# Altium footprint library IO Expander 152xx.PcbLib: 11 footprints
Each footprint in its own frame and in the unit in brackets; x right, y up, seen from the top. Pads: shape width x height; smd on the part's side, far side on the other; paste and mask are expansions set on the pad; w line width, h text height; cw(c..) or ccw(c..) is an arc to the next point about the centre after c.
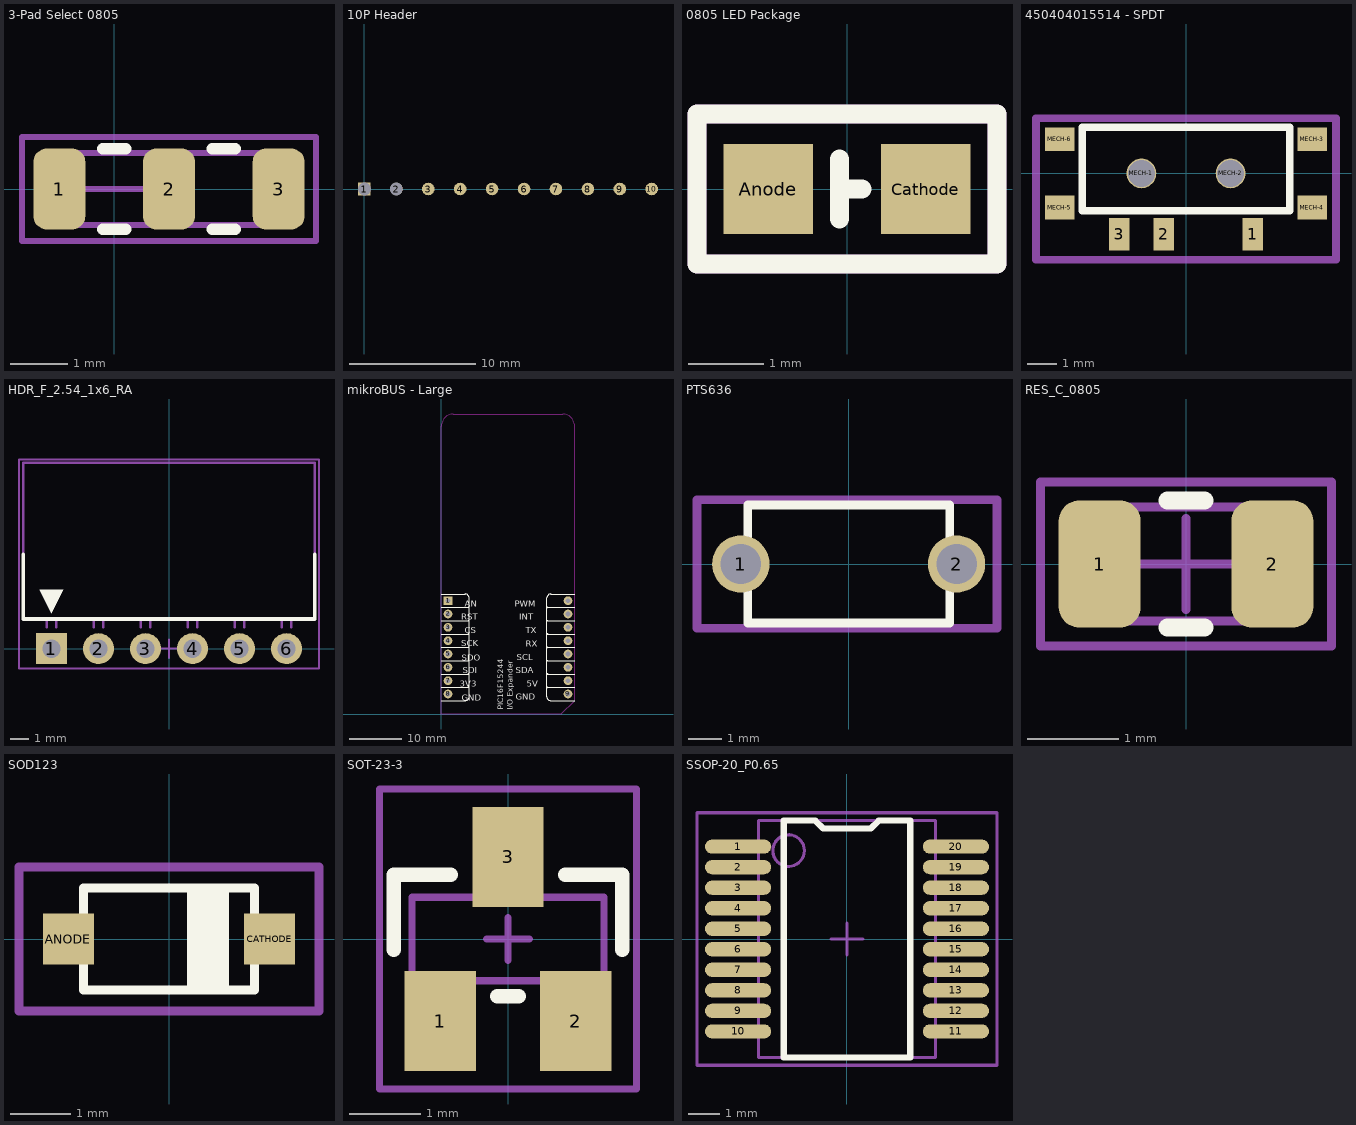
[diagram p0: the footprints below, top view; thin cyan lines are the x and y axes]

## 3-Pad Select 0805 [mm] "Chip Resistor, 2-Leads, Body 2.0x1.3mm, IPC Medium Density"
height 0.6
pads (3):
  rrect50% 0.9x1.4 smd: 1(-0.95,0) 2(0.95,0) 3(2.85,0)
Top Overlay:
  lines w0.2: -0.2,-0.7 0.2,-0.7 ; -0.2,0.7 0.2,0.7 ; 1.7,-0.7 2.1,-0.7 ; 1.7,0.7 2.1,0.7
Top Assembly:
  lines w0.1: -1,-0.625 -1,0.625 2.6,0.625 2.6,-0.625 -1,-0.625
  text ".Designator" at -0.8,-0.2 h0.45
Top 3D Body:
  lines w0.1: 0.6,-0.625 2.6,-0.625 ; 0.6,0.625 2.6,0.625 ; 2.6,-0.625 2.6,0.625 ; 2.6,-0.625 -1,-0.625 -1,0.625 2.6,0.625
Top Courtyard:
  lines w0.1: -0.5,0 0.5,0 ; -1.6,-0.9 3.5,-0.9 3.5,0.9 -1.6,0.9 -1.6,-0.9
3D body "RES_0805.step": height 0.78, standoff 0, extent -1,-0.625 1,0.625
3D body "RES_0805.step": height 0.78, standoff 0, extent 0.6,-0.625 2.6,0.625

## 10P Header [mm] "Footprint for 10P 2.54mm Header"
pads (10):
  rect 1x1 hole 1.02: 1(0,0)
  round 1 hole 1.02: 2(2.54,0)
  round 1 all layers, no hole: 3(5.08,0) 4(7.62,0) 5(10.16,0) 6(12.7,0) 7(15.24,0) 8(17.78,0) 9(20.32,0) 10(22.86,0)

## 0805 LED Package [mm] "0805 Package for LED"
height 2.6
pads (2):
  rect 1.2x1.2 smd: Anode(-1.05,0) Cathode(1.05,0)
Top Overlay:
  lines w0.254: -0.1,-0.4 -0.1,0.4 ; -0.1,0 0.2,0 ; -2,-1 -2,1 2,1 2,-1 -2,-1
Top Courtyard:
  lines w0.254: -2,-1 -2,1 2,1 2,-1 -2,-1
  text ".designator" at -1.8,-0.367 h1

## 450404015514 - SPDT [mm] "SPDT Switch"
pads (9):
  rect 0.7x1.1 smd: 1(2.25,-2.05) 2(-0.75,-2.05) 3(-2.25,-2.05)
  round 1 hole 0.9 unplated: MECH-1(-1.5,0) MECH-2(1.5,0)
  rect 1x0.8 smd: MECH-3(4.25,1.15) MECH-4(4.25,-1.15) MECH-5(-4.25,-1.15) MECH-6(-4.25,1.15)
Top Overlay:
  lines w0.254: -3.5,-1.25 3.5,-1.25 3.5,1.55 -3.5,1.55 -3.5,-1.25
Top Courtyard:
  lines w0.254: -5.05,-2.9 5.05,-2.9 5.05,1.85 -5.05,1.85 -5.05,-2.9

## HDR_F_2.54_1x6_RA [mil] "Header Female Right Angle 6 Way 2.54mm Pitch"
height 102.36
pads (6):
  rect 66x66 hole 39: 1(-250,0)
  round 66 hole 39: 2(-150,0) 3(-50,0) 4(50,0) 5(150,0) 6(250,0)
Top Overlay:
  region: -250,75 -275,125 -225,125
  lines w7.87: -310,200 -310,62.99 310,62.99 310,200
Top Assembly:
  lines w5: -260,45 -260,65 ; -240,45 -240,65 ; -160,45 -160,65 ; -140,45 -140,65 ; -60,45 -60,65 ; -40,45 -40,65 ; 40,45 40,65 ; 60,45 60,65 ; 140,45 140,65 ; 160,45 160,65 ; 240,45 240,65 ; 260,45 260,65 ; -310,65 -310,395 310,395 310,65 -310,65
  text ".Designator" at -5,75 h30
Top Courtyard:
  lines w3.94: -19.68,0 19.68,0 ; 0,-19.68 0,19.68 ; -319,-42 319,-42 319,402 -319,402 -319,-42
3D body "HDR_F_254_1x6 RA.step": height 96.71, standoff -98.29, extent -309.99,-7.99 310.01,395

## mikroBUS - Large [mil]
height 47.24
pads (16):
  rect 65x65 hole 35: 1(50,850)
  round 65 hole 35: 2(50,750) 3(50,650) 4(50,550) 5(50,450) 6(50,350) 7(50,250) 8(50,150) 9(950,150) 10(950,250) 11(950,350) 12(950,450) 13(950,550) 14(950,650) 15(950,750) 16(950,850)
Top Overlay:
  lines w6: 0,100 180.05,100 ; 0,900 180,900 cw(c180,872.05) 207.95,872.05 ; 180.05,100.05 ccw(c180.05,128) 208,128 208,872.05 ; 208,805 cw(c203,805) 203,800 ; 792,805 ccw(c797,805) 797,800 ; 792,872.05 792,128 ccw(c819.95,128) 819.95,100.05 ; 792.05,872.05 cw(c820,872.05) 820,900 1000,900 ; 819.95,100 1000,100 ; 203,200 cw(c203,195) 208,195 ccw(c203,195) 203,200 ; 203,200 ccw(c203,205) 208,205 208,295 ; 203,200 0,200 203,200 ; 203,300 cw(c203,295) 208,295 ; 203,300 ccw(c203,305) 208,305 208,395 ; 203,300 cw(c203,295) 208,295 ; 203,300 0,300 203,300 ; 203,400 cw(c203,395) 208,395 ; 203,400 ccw(c203,405) 208,405 208,495 ; 203,400 cw(c203,395) 208,395 ; 203,400 0,400 203,400 ; 203,500 cw(c203,495) 208,495 ; 203,500 ccw(c203,505) 208,505 208,595 ; 203,500 cw(c203,495) 208,495 ; 203,500 0,500 203,500 ; 203,600 cw(c203,595) 208,595 ; 203,600 ccw(c203,605) 208,605 208,695 ; 203,600 cw(c203,595) 208,595 ; 203,600 0,600 203,600 ; 203,700 cw(c203,695) 208,695 ; 203,700 ccw(c203,705) 208,705 208,795 ; 203,700 cw(c203,695) 208,695 ; 203,700 0,700 203,700 ; 203,800 cw(c203,795) 208,795 ; 203,800 cw(c203,795) 208,795 ; 203,800 0,800 203,800 ; 792,295 cw(c797,295) 797,300 ; 792,295 cw(c797,295) 797,300 ; 792,295 792,205 ccw(c797,205) 797,200 ; 792,395 cw(c797,395) 797,400 ; 792,395 cw(c797,395) 797,400 ; 792,395 792,305 ccw(c797,305) 797,300 ; 792,495 cw(c797,495) 797,500 ; 792,495 cw(c797,495) 797,500 ; 792,495 792,405 ccw(c797,405) 797,400 ; 792,595 cw(c797,595) 797,600 ; 792,595 cw(c797,595) 797,600 ; 792,595 792,505 ccw(c797,505) 797,500 ; 792,695 cw(c797,695) 797,700 ; 792,695 cw(c797,695) 797,700 ; 792,695 792,605 ccw(c797,605) 797,600 ; 792,795 cw(c797,795) 797,800 ; 792,795 cw(c797,795) 797,800 ; 792,795 792,705 ccw(c797,705) 797,700 ; 797,200 ccw(c797,195) 792,195 cw(c797,195) 797,200 ; 797,200 1000,200 797,200 ; 797,300 1000,300 797,300 ; 797,400 1000,400 797,400 ; 797,500 1000,500 797,500 ; 797,600 1000,600 797,600 ; 797,700 1000,700 797,700 ; 797,800 1000,800 797,800
  text "PIC16F15244 / I/O Expander" at 550,30 h70.87
  text "CS" at 175,590 h78.74
  text "PWM" at 550,790 h78.74
  text "INT" at 585,690 h78.74
  text "TX" at 634.78,590 h78.74
  text "RX" at 634.78,488.89 h78.74
  text "SCL" at 565,389.55 h78.74
  text "SDA" at 560,290 h78.74
  text "5V" at 640,190 h78.74
  text "GND" at 560,90 h78.74
  text "AN" at 175,790 h78.74
  text "GND" at 155,85 h78.74
  text "3V3" at 140,190 h78.74
  text "SDI" at 160.31,290 h78.74
  text "SDO" at 155,385 h78.74
  text "SCK" at 150,495 h78.74
  text "RST" at 150,690 h78.74
Bottom Overlay:
  lines w6: 0,100 221.05,100 ; 0,900 221,900 cw(c221,872.05) 248.95,872.05 248.95,128.05 ; 221.05,100.05 ccw(c221.05,128) 249,128 ; 249,128.05 249,195 ccw(c244,195) 244,200 ; 249,805 cw(c244,805) 244,800 ; 751,128 ccw(c778.95,128) 778.95,100.05 ; 751,128.05 751,195 cw(c756,195) 756,200 ; 751,805 ccw(c756,805) 756,800 ; 751.05,128.05 751.05,872.05 cw(c779,872.05) 779,900 1000,900 ; 778.95,100 1000,100 ; 244,200 ccw(c244,205) 249,205 249,295 ccw(c244,295) 244,300 ; 244,200 0,200 244,200 ; 244,300 ccw(c244,305) 249,305 249,395 ccw(c244,395) 244,400 ; 244,300 0,300 244,300 ; 244,400 ccw(c244,405) 249,405 249,495 ccw(c244,495) 244,500 ; 244,400 0,400 244,400 ; 244,500 ccw(c244,505) 249,505 249,595 ccw(c244,595) 244,600 ; 244,500 0,500 244,500 ; 244,600 ccw(c244,605) 249,605 249,695 ccw(c244,695) 244,700 ; 244,600 0,600 244,600 ; 244,700 ccw(c244,705) 249,705 249,795 ccw(c244,795) 244,800 ; 244,700 0,700 244,700 ; 244,800 0,800 244,800 ; 756,200 cw(c756,205) 751,205 751,295 cw(c756,295) 756,300 ; 756,200 1000,200 756,200 ; 756,300 cw(c756,305) 751,305 751,395 cw(c756,395) 756,400 ; 756,300 1000,300 756,300 ; 756,400 cw(c756,405) 751,405 751,495 cw(c756,495) 756,500 ; 756,400 1000,400 756,400 ; 756,500 cw(c756,505) 751,505 751,595 cw(c756,595) 756,600 ; 756,500 1000,500 756,500 ; 756,600 cw(c756,605) 751,605 751,695 cw(c756,695) 756,700 ; 756,600 1000,600 756,600 ; 756,700 cw(c756,705) 751,705 751,795 cw(c756,795) 756,800 ; 756,700 1000,700 756,700 ; 756,800 1000,800 756,800
  text "PWM" at 756,805 h78.74
  text "INT" at 751.05,700 h78.74
  text "TX" at 740,605 h78.74
  text "RX" at 740,503 h78.74
  text "SCL" at 750,405 h78.74
  text "SDA" at 751.05,300 h78.74
  text "5V" at 740,205 h78.74
  text "GND" at 756,103 h78.74
  text "RST" at 435,705 h78.74
  text "CS" at 385,605 h78.74
  text "SCK" at 445.8,503 h78.74
  text "SDO" at 450,405 h78.74
  text "SDI" at 405,303 h78.74
  text "3V3" at 415,205 h78.74
  text "GND" at 450,103 h78.74
  text "AN" at 388.71,805 h78.74
Keep-Out Layer:
  lines w6: 0,0 0,2160 cw(c90,2160) 90,2250 910,2250 cw(c910,2160) 1000,2160 1000,100 900,0 0,0
3D body "Header 1x8.stp": height 81.88, standoff -398.04, extent 895,100 1009.96,900
3D body "Header 1x8.stp": height 81.88, standoff -398.04, extent -5,100 109.96,900

## PTS636 [mm] "PTS636 TH Switch, 6mm x 3.5mm, 4.5mm Tall"
pads (2):
  round 1.702 hole 1.2: 1(-3.2,0) 2(3.2,0)
Top Overlay:
  lines w0.254: -3,-1.75 3,-1.75 3,1.75 -3,1.75 -3,-1.75
Top Courtyard:
  lines w0.254: -4.5,-1.9 4.4,-1.9 4.4,1.9 -4.5,1.9 -4.5,-1.9

## RES_C_0805 [mm] "Chip Resistor, 2-Leads, Body 2.0x1.3mm, IPC Medium Density"
height 0.6
pads (2):
  rrect50% 0.9x1.4 smd: 1(-0.95,0) 2(0.95,0)
Top Overlay:
  lines w0.2: -0.2,-0.7 0.2,-0.7 ; -0.2,0.7 0.2,0.7
Top Assembly:
  lines w0.1: -1,-0.625 1,-0.625 1,0.625 -1,0.625 -1,-0.625
  text ".Designator" at -0.8,-0.2 h0.45
Top 3D Body:
  lines w0.1: -1,-0.625 -1,0.625 1,0.625 1,-0.625 -1,-0.625
Top Courtyard:
  lines w0.1: -0.5,0 0.5,0 ; 0,-0.5 0,0.5 ; -1.6,-0.9 -1.6,0.9 1.6,0.9 1.6,-0.9 -1.6,-0.9
3D body "RES_0805.step": height 0.78, standoff 0, extent -1,-0.625 1,0.625

## SOD123 [mm]
pads (2):
  rect 0.85x0.85 smd: ANODE(-1.675,0) CATHODE(1.675,0)
Top Overlay:
  rectangle: 0.3,-0.8 1,0.8
  lines w0.152: -1.425,-0.85 -1.425,0.85 1.425,0.85 1.425,-0.85 -1.425,-0.85
Top Courtyard:
  lines w0.152: -2.5,-1.2 -2.5,1.2 2.5,1.2 2.5,-1.2 -2.5,-1.2
  text "'.Designator'" at -0.9,-0.267 h1

## SOT-23-3 [mm]
height 2.6
pads (3):
  rect 1x1.4 smd: 1(-0.95,-1.15) 2(0.95,-1.15) 3(0,1.15)
Top Overlay:
  lines w0.2: -1.6,-0.15 -1.6,0.9 -0.8,0.9 ; -0.15,-0.8 0.15,-0.8 ; 0.8,0.9 1.6,0.9 1.6,-0.15
Top Assembly:
  lines w0.1: -1.13,-0.584 -1.13,-1.168 -0.775,-1.168 -0.775,-0.584 ; -0.175,0.584 -0.175,1.168 0.18,1.168 0.18,0.584 ; 0.77,-0.584 0.77,-1.168 1.125,-1.168 1.125,-0.584 ; -1.346,-0.584 -1.346,0.584 1.346,0.584 1.346,-0.584 -1.346,-0.584
  text ".Designator" at -1.7,-0.3 h0.8
Top Courtyard:
  lines w0.1: -0.3,0 0.3,0 ; 0,-0.3 0,0.3 ; -1.8,-2.1 -1.8,2.1 1.8,2.1 1.8,-2.1 -1.8,-2.1
3D body "SOT-23.step": height 1.09, standoff -0.01, extent -1.5,-1.25 1.5,1.25

## SSOP-20_P0.65 [mm] "SOP, 20-Leads, Body 7.5x5.6mm (max), Pitch 0.65mm, IPC Medium Density"
height 2
pads (20):
  oval 2.1x0.45 smd mask+0.05: 1(-3.45,2.925) 2(-3.45,2.275) 3(-3.45,1.625) 4(-3.45,0.975) 5(-3.45,0.325) 6(-3.45,-0.325) 7(-3.45,-0.975) 8(-3.45,-1.625) 9(-3.45,-2.275) 10(-3.45,-2.925) 11(3.45,-2.925) 12(3.45,-2.275) 13(3.45,-1.625) 14(3.45,-0.975) 15(3.45,-0.325) 16(3.45,0.325) 17(3.45,0.975) 18(3.45,1.625) 19(3.45,2.275) 20(3.45,2.925)
Top Overlay:
  lines w0.2: -2,-3.75 -2,3.75 -1,3.75 -0.75,3.5 0.75,3.5 1,3.75 2,3.75 2,-3.75 -2,-3.75
  text "." at -2.8,3.75 h1
Top Assembly:
  lines w0.1: -2,-3.75 2,-3.75 2,3.75 1,3.75 0.75,3.5 -0.75,3.5 -1,3.75 -2,3.75 -2,-3.75
  text "1" at -3.8,3.1 h1
  text ".Designator" at 0.5,-1.7 h1
Top 3D Body:
  circle w0.1: c-1.85,2.8 r0.5
  lines w0.1: -2.8,-3.75 -2.8,3.75 2.8,3.75 2.8,-3.75 -2.8,-3.75
Top Courtyard:
  lines w0.1: -0.5,0 0.5,0 ; 0,-0.5 0,0.5 ; -4.75,-4 -4.75,4 4.75,4 4.75,-4 -4.75,-4
3D body "SSOP-20.step": height 1.95, standoff -0.04, extent -3.95,-3.655 3.95,3.675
